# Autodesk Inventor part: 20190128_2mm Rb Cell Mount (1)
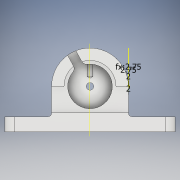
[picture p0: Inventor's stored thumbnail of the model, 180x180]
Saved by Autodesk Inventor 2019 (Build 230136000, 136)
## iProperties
Created: 2018-07
Part Number: 20190128_2mm Rb Cell Mount (1)
Material: PC/ABS Plastic
Document SubType Name: Modeling
Designer: Renju
Density: 0.357273 g/cm^3
Appearance: Smooth - White
Author: Renju
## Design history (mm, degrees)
sketch "Sketch1"
  geometry: L1 (0, -20.2)-(22.2, -20.2); L2 (22.2, -20.2)-(22.2, 20.2); L3 (22.2, 20.2)-(0, 20.2); L4 (0, 20.2)-(0, -20.2); C1 r 2 at (0, 0); A1 r 20.2 centre (0, 0) between (0, -20.2) and (0, 20.2); 1 further point
  constraints: 8 end point, 2 centre point, 2 coincident, 2 parallel, 2 point on circle, 1 horizontal, 1 perpendicular
  dimensions: "d0" = 40.4 diameter of A1; "d1" = 4 diameter of C1; "d163" = 22.2 distance from line of A1.centre L2 (computed from d0)
extrude "Extrusion1" new body sketch "Sketch1" distance "d2" = 12; taper "d3" = 0 deg
sketch "Sketch2"
  geometry: C1 r 13.7 at (0, 0); 1 further point
  constraints: 1 centre point, 1 coincident
  dimensions: "d4" = 27.4 diameter of C1
extrude "Extrusion2" cut sketch "Sketch2" distance "d5" = 2; taper "d6" = 0 deg
sketch "Sketch3"
  geometry: C1 r 11.75 at (0, 0); 1 further point
  constraints: 1 centre point, 1 coincident
  dimensions: "d9" = 23.5 diameter of C1
extrude "Extrusion3" cut sketch "Sketch3" distance "d10" = 8.1; taper "d11" = 0 deg
workplane "Work Plane1"
sketch "Sketch6"
  geometry: L1 (0.017, -0.764)-(0.017, 21.531); L2 (20.2, 12)-(0, 12) reference; 3 further points
  constraints: 2 end point, 1 vertical
  dimensions: "d13" = 2.75 distance from line of L2 point (2.017, 9.25) (= d17); "d14" = 2 distance from line of L1 point (2.017, 9.25); "d16" = 2 distance from line of point (-1.983, 9.25) L1; "d17" = 2.75 distance from line of L2 point (-1.983, 9.25)
workplane "Work Plane2"
sketch "Sketch12"
  geometry: L1 (0, 14.4)-(0, -2.4) reference; L2 (-20.2, 0)-(20.2, 0) reference; L3 (-11.75, 1.9)-(11.75, 1.9) reference; 2 further points
  constraints: 1 midpoint
hole "Hole2" sketch "Sketch12" at (0, 1.9) diameter "d33" = 3; stored, may be unused: countersink angle "d37" = 90 deg, drill point angle "d39" = 118 deg; dims "d34" = 6, "d35" = 4, "d36" = 2, "d38" = 15
sketch "Sketch24"
  geometry: L1 (4.141, -7.582)-(11, -20.139); L2 (1.947, -8.78)-(8.806, -21.337); L3 (13.194, -18.94)-(6.335, -6.383); L4 (0, -32.677)-(0, 31.346) reference; L5 (0, 0)-(11, -20.139); C1 r 20.2 at (0, 0) reference; C2 r 2 at (0, 0) reference; A1 r 2.5 centre (4.141, -7.582) between (6.335, -6.383) and (1.947, -8.78); A2 r 2.5 centre (11, -20.139) between (8.806, -21.337) and (13.194, -18.94); 2 further points
  constraints: 10 end point, 4 point on circle, 4 tangent, 2 centre point, 1 collinear, 1 midpoint, 1 parallel
  dimensions: "d77" = 5 diameter of A2; "d81" = 11 distance from line of L4 L1.end (= d56)
extrude "Extrusion5" cut sketch "Sketch24" stored distance "d78" = 7.9; taper "d79" = 0 deg
sketch "Sketch25"
  geometry: L1 (16, -44.75)-(24, -44.75); L2 (24, -44.75)-(24, 44.75); L3 (24, 44.75)-(16, 44.75); L4 (16, 44.75)-(16, -44.75); L5 (-29.04, 0)-(32.84, 0) reference; 1 further point
  constraints: 8 end point, 2 parallel, 1 horizontal, 1 perpendicular
  dimensions: "d85" = 44.75 distance between parallel lines of L1 L5; "d86" = 89.5 distance between parallel lines of L3 L1 (= 2 x d85); "d114" = 8 distance between parallel lines of L4 L2
extrude "Extrusion6" join sketch "Sketch25" stored distance "d87" = 11.7; taper "d88" = 0 deg; dims "d123" = 0.55, "d124" = 0
sketch "Sketch37"
  geometry: L1 (-11.7, 0)-(0.3, 0) reference; L2 (-5.7, 0)-(-5.7, 89.5); L3 (0.3, 89.5)-(-11.7, 89.5) reference; L4 (-5.7, 6.25)-(-5.7, 17.3); L5 (-3.45, 6.25)-(-3.45, 17.3); L6 (-7.95, 17.3)-(-7.95, 6.25); L7 (-5.7, 83.25)-(-5.7, 72.2); L8 (-7.95, 83.25)-(-7.95, 72.2); L9 (-3.45, 72.2)-(-3.45, 83.25); L10 (-11.7, 32.947)-(-11.7, 24.55) reference; L11 (-11.7, 32.947)-(-1.6, 32.947) reference; L12 (-1.6, 32.947)-(-1.6, 37.335) reference; L13 (-1.6, 37.335)-(-11.7, 37.335) reference; L14 (-11.7, 64.95)-(-11.7, 37.335) reference; L15 (0.3, 24.55)-(0.3, 64.95) reference; L16 (0.3, 24.55)-(-11.7, 24.55) reference; L17 (0.3, 64.95)-(-11.7, 64.95) reference; L18 (0.3, 64.95)-(-11.7, 64.95) reference; L19 (0.3, 24.55)-(-11.7, 24.55) reference; L20 (0.3, 89.5)-(0.3, 0) reference; L21 (-11.7, 89.5)-(-11.7, 0) reference; A1 r 2.25 centre (-5.7, 6.25) between (-7.95, 6.25) and (-3.45, 6.25); A2 r 2.25 centre (-5.7, 17.3) between (-3.45, 17.3) and (-7.95, 17.3); A3 r 2.25 centre (-5.7, 83.25) between (-3.45, 83.25) and (-7.95, 83.25); A4 r 2.25 centre (-5.7, 72.2) between (-7.95, 72.2) and (-3.45, 72.2); 7 further points
  constraints: 18 end point, 8 point on circle, 8 tangent, 4 centre point, 4 midpoint, 4 point on line, 2 parallel
  dimensions: "d146" = 4.5 diameter of A2; "d147" = 4.5 diameter of A4; "d148" = 77 distance of L7.start L4.start; "d149" = 6.25 distance from line of L1 L4.start (= d150); "d150" = 6.25 distance from line of L3 L7.start (derived); "d151" = 7.25 distance from line of L17 L7.end (computed from d153); "d152" = 7.25 distance from line of L16 L4.end (= d151); "d153" = 2.25 radius of A4 (derived); "d188" = 6 distance between parallel lines of L20 L2 (derived); "d189" = 6 distance between parallel lines of L21 L2 (derived)
extrude "Extrusion12" cut sketch "Sketch37" extent not by distance; stored distance "d154" = 5; taper "d155" = 0 deg
fillet "Fillet7" dims "d159" = 5
fillet "Fillet8" dims "d164" = 2
sketch "Sketch42"
  geometry: C1 r 2 at (0, 0); 1 further point
  constraints: 1 centre point, 1 coincident
  dimensions: "d165" = 4 diameter of C1
extrude "Extrusion14" cut sketch "Sketch42" extent not by distance; stored distance "d166" = 5; taper "d167" = 0 deg
fillet "Fillet9" dims "d168" = 2.8
sketch "Sketch49"
  geometry: L1 (14, 20.2)-(0, 20.2) reference; L2 (14, -20.2)-(0, -20.2); L3 (0, -20.2)-(0, 20.2); L4 (0, 20.2)-(14, 20.2); L5 (14, 20.2)-(14, -20.2); A1 r 2 centre (14, -22.2) between (16, -22.2) and (14, -20.2) reference; 1 further point
  constraints: 8 end point, 2 parallel, 1 horizontal, 1 perpendicular
extrude "Extrusion18" cut sketch "Sketch49" stored distance "d190" = 10; taper "d191" = 0 deg
sketch "Sketch50" dims "d194" = 2
  geometry: L1 (14, -10)-(14, 0) reference; L2 (0, 0)-(0, -10) reference; L3 (14, -4)-(0, -4); L4 (0, -4)-(0, -2); L5 (0, -2)-(14, -2); L6 (14, -2)-(14, -4); L7 (0, -10)-(14, -10) reference
  constraints: 8 end point, 2 parallel, 2 point on line, 1 horizontal, 1 perpendicular
  dimensions: "d192" = 2 distance of L3.end L4.end; "d193" = 6 distance between parallel lines of L3 L7
extrude "Extrusion19" cut sketch "Sketch50" distance "d194" = 2; taper "d195" = 0 deg
sketch "Sketch51"
  geometry: L1 (0, 0)-(0, 10) reference; L2 (14, 10)-(14, 0) reference; L3 (0, 4)-(14, 4); L4 (14, 4)-(14, 2); L5 (14, 2)-(0, 2); L6 (0, 2)-(0, 4); L7 (14, 10)-(0, 10) reference
  constraints: 8 end point, 2 parallel, 2 point on line, 1 horizontal, 1 perpendicular
  dimensions: "d196" = 2 distance of L3.end L4.end; "d197" = 6 distance between parallel lines of L7 L3
extrude "Extrusion20" cut sketch "Sketch51" distance "d198" = 2; taper "d199" = 0 deg
body "Solid1" dims "d13" = 2.75 (= d17)
node "Projected Loop3"
other parameters: "d56" = 11 (derived)
